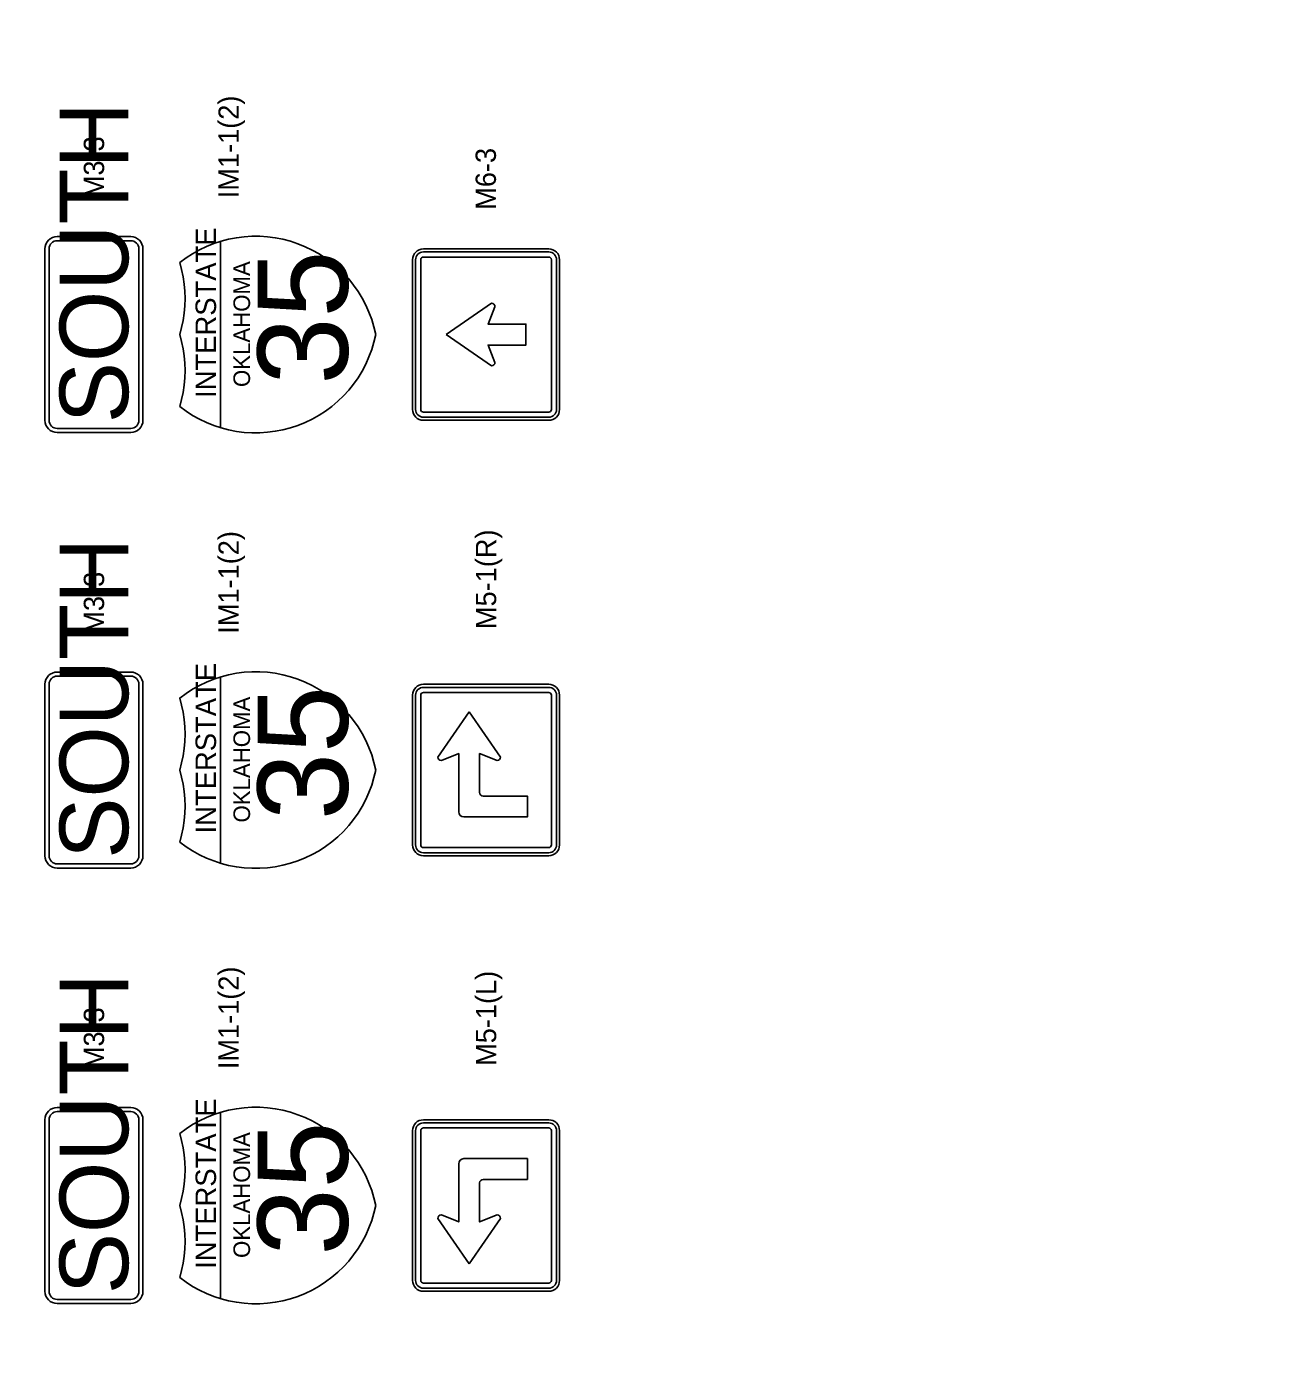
# Model space of a CAD drawing. Extents: x 2135767 to 2151731, y 141839 to 175894.
# Drawn here: x 2137979.7 to 2138264.3, y 170041.1 to 170345.9 of the extents above; entities that cross this region are included whole.
import ezdxf

# ---------------------------------------------------------------- set-up
doc = ezdxf.new("R2010")
doc.units = 0
doc.layers.add('PR_Phasing_Detour_1', color=7, linetype='Continuous')

msp = doc.modelspace()

# ---------------------------------------------------------------- linework, layer by layer
at = {"layer": 'PR_Phasing_Detour_1'}
for p, q in [((2138003.64, 170297.62), (2137986.76, 170297.62)), ((2138003.64, 170296.68), (2137986.76, 170296.68)), ((2138024.26, 170253.71), (2138024.26, 170296.55)), ((2137983.95, 170294.81), (2137983.95, 170255.43)), ((2137984.89, 170294.81), (2137984.89, 170255.43)), ((2138005.51, 170255.43), (2138005.51, 170294.81)), ((2138006.45, 170255.43), (2138006.45, 170294.81)), ((2138099.58, 170294.81), (2138070.82, 170294.81)), ((2138099.58, 170294.1), (2138070.82, 170294.1)), ((2138099.58, 170294.1), (2138070.82, 170294.1)), ((2138070.82, 170292.93), (2138099.58, 170292.93)), ((2138070.82, 170292.93), (2138099.58, 170292.93)), ((2138068.32, 170292.31), (2138068.32, 170257.92)), ((2138069.03, 170292.31), (2138069.03, 170257.92)), ((2138069.03, 170292.31), (2138069.03, 170257.92)), ((2138070.2, 170257.92), (2138070.2, 170292.31)), ((2138070.2, 170257.92), (2138070.2, 170292.31)), ((2138100.2, 170292.31), (2138100.2, 170257.92)), ((2138100.2, 170292.31), (2138100.2, 170257.92)), ((2138101.37, 170257.92), (2138101.37, 170292.31)), ((2138101.37, 170257.92), (2138101.37, 170292.31)), ((2138102.07, 170257.92), (2138102.07, 170292.31)), ((2138086.45, 170282.31), (2138076.06, 170275.12)), ((2138085.65, 170277.52), (2138087.24, 170281.51)), ((2138094.34, 170277.52), (2138085.65, 170277.52)), ((2138094.34, 170272.72), (2138094.34, 170277.52)), ((2138076.06, 170275.12), (2138086.45, 170267.93)), ((2138087.24, 170268.73), (2138085.65, 170272.72)), ((2138085.65, 170272.72), (2138094.34, 170272.72)), ((2138099.58, 170257.31), (2138070.82, 170257.31)), ((2138099.58, 170257.31), (2138070.82, 170257.31)), ((2138070.82, 170256.13), (2138099.58, 170256.13)), ((2138070.82, 170256.13), (2138099.58, 170256.13)), ((2137986.76, 170253.56), (2138003.64, 170253.56)), ((2138070.82, 170255.43), (2138099.58, 170255.43)), ((2137986.76, 170252.62), (2138003.64, 170252.62)), ((2138003.64, 170197.62), (2137986.76, 170197.62)), ((2138003.64, 170196.68), (2137986.76, 170196.68)), ((2138024.26, 170153.71), (2138024.26, 170196.55)), ((2137983.95, 170194.81), (2137983.95, 170155.43)), ((2137984.89, 170194.81), (2137984.89, 170155.43)), ((2138005.51, 170155.43), (2138005.51, 170194.81)), ((2138006.45, 170155.43), (2138006.45, 170194.81)), ((2138068.32, 170192.31), (2138068.32, 170157.92)), ((2138069.03, 170192.31), (2138069.03, 170157.92)), ((2138069.03, 170192.31), (2138069.03, 170157.92)), ((2138070.2, 170192.31), (2138070.2, 170157.92)), ((2138070.2, 170157.92), (2138070.2, 170192.31)), ((2138099.58, 170194.81), (2138070.82, 170194.81)), ((2138099.58, 170194.1), (2138070.82, 170194.1)), ((2138099.58, 170194.1), (2138070.82, 170194.1)), ((2138099.58, 170192.93), (2138070.82, 170192.93)), ((2138070.82, 170192.93), (2138099.58, 170192.93)), ((2138100.2, 170157.92), (2138100.2, 170192.31)), ((2138100.2, 170192.31), (2138100.2, 170157.92)), ((2138101.37, 170157.92), (2138101.37, 170192.31)), ((2138101.37, 170157.92), (2138101.37, 170192.31)), ((2138102.07, 170157.92), (2138102.07, 170192.31)), ((2138074.14, 170178.09), (2138081.33, 170188.48)), ((2138081.33, 170188.48), (2138088.52, 170178.09)), ((2138078.93, 170178.89), (2138074.94, 170177.29)), ((2138078.93, 170165.54), (2138078.93, 170178.89)), ((2138087.72, 170177.29), (2138083.73, 170178.89)), ((2138083.73, 170178.89), (2138083.73, 170169.94)), ((2138084.53, 170169.14), (2138094.69, 170169.14)), ((2138094.69, 170169.14), (2138094.69, 170164.35)), ((2138094.69, 170164.35), (2138080.13, 170164.35)), ((2138070.82, 170157.31), (2138099.58, 170157.31)), ((2138099.58, 170157.31), (2138070.82, 170157.31)), ((2138070.82, 170156.13), (2138099.58, 170156.13)), ((2138070.82, 170156.13), (2138099.58, 170156.13)), ((2138070.82, 170155.43), (2138099.58, 170155.43)), ((2137986.76, 170153.56), (2138003.64, 170153.56)), ((2137986.76, 170152.62), (2138003.64, 170152.62)), ((2138003.64, 170097.62), (2137986.76, 170097.62)), ((2137983.95, 170094.81), (2137983.95, 170055.43)), ((2137984.89, 170094.81), (2137984.89, 170055.43)), ((2138003.64, 170096.68), (2137986.76, 170096.68)), ((2138005.51, 170055.43), (2138005.51, 170094.81)), ((2138006.45, 170055.43), (2138006.45, 170094.81)), ((2138024.26, 170053.71), (2138024.26, 170096.55)), ((2138099.58, 170094.81), (2138070.82, 170094.81)), ((2138068.32, 170092.31), (2138068.32, 170057.92)), ((2138069.03, 170092.31), (2138069.03, 170057.92)), ((2138069.03, 170092.31), (2138069.03, 170057.92)), ((2138070.2, 170092.31), (2138070.2, 170057.92)), ((2138070.2, 170057.92), (2138070.2, 170092.31)), ((2138099.58, 170094.1), (2138070.82, 170094.1)), ((2138099.58, 170094.1), (2138070.82, 170094.1)), ((2138099.58, 170092.93), (2138070.82, 170092.93)), ((2138070.82, 170092.93), (2138099.58, 170092.93)), ((2138100.2, 170057.92), (2138100.2, 170092.31)), ((2138100.2, 170092.31), (2138100.2, 170057.92)), ((2138101.37, 170057.92), (2138101.37, 170092.31)), ((2138101.37, 170057.92), (2138101.37, 170092.31)), ((2138102.07, 170057.92), (2138102.07, 170092.31)), ((2138094.69, 170085.89), (2138080.13, 170085.89)), ((2138094.69, 170081.1), (2138094.69, 170085.89)), ((2138078.93, 170084.69), (2138078.93, 170071.35)), ((2138083.73, 170071.35), (2138083.73, 170080.3)), ((2138084.53, 170081.1), (2138094.69, 170081.1)), ((2138074.14, 170072.15), (2138081.33, 170061.76)), ((2138078.93, 170071.35), (2138074.94, 170072.94)), ((2138081.33, 170061.76), (2138088.52, 170072.15)), ((2138087.72, 170072.94), (2138083.73, 170071.35)), ((2138070.82, 170057.31), (2138099.58, 170057.31)), ((2138099.58, 170057.31), (2138070.82, 170057.31)), ((2138070.82, 170056.13), (2138099.58, 170056.13)), ((2138070.82, 170056.13), (2138099.58, 170056.13)), ((2138070.82, 170055.43), (2138099.58, 170055.43)), ((2137986.76, 170053.56), (2138003.64, 170053.56)), ((2137986.76, 170052.62), (2138003.64, 170052.62))]:
    msp.add_line(p, q, dxfattribs=at)
for points in [[(2138014.89, 170258.59), (2138016.33, 170257.52), (2138017.84, 170256.55), (2138019.4, 170255.68), (2138021.02, 170254.9), (2138022.69, 170254.24), (2138024.39, 170253.68), (2138026.12, 170253.23), (2138027.89, 170252.89), (2138029.66, 170252.66), (2138031.45, 170252.55), (2138033.25, 170252.55), (2138035.04, 170252.67), (2138036.82, 170252.9), (2138038.58, 170253.24), (2138040.31, 170253.7), (2138042.01, 170254.26), (2138043.68, 170254.93), (2138045.29, 170255.71), (2138046.86, 170256.59), (2138048.36, 170257.56), (2138049.8, 170258.63), (2138051.17, 170259.79), (2138052.46, 170261.04), (2138053.67, 170262.36), (2138054.79, 170263.76), (2138055.82, 170265.22), (2138056.76, 170266.75), (2138057.6, 170268.34), (2138058.33, 170269.98), (2138058.96, 170271.66), (2138059.48, 170273.37), (2138059.89, 170275.12), (2138059.48, 170276.86), (2138058.96, 170278.58), (2138058.33, 170280.26), (2138057.6, 170281.9), (2138056.76, 170283.48), (2138055.82, 170285.01), (2138054.79, 170286.48), (2138053.67, 170287.88), (2138052.46, 170289.2), (2138051.17, 170290.44), (2138049.8, 170291.6), (2138048.36, 170292.67), (2138046.86, 170293.65), (2138045.29, 170294.53), (2138043.68, 170295.3), (2138042.01, 170295.97), (2138040.31, 170296.54), (2138038.58, 170296.99), (2138036.82, 170297.34), (2138035.04, 170297.57), (2138033.25, 170297.68), (2138031.45, 170297.69), (2138029.66, 170297.57), (2138027.89, 170297.35), (2138026.12, 170297.01), (2138024.39, 170296.56), (2138022.69, 170296), (2138021.02, 170295.33), (2138019.4, 170294.56), (2138017.84, 170293.69), (2138016.33, 170292.72), (2138014.89, 170291.65), (2138015.33, 170290.03), (2138015.68, 170288.39), (2138015.93, 170286.73), (2138016.08, 170285.06), (2138016.13, 170283.38), (2138016.08, 170281.71), (2138015.93, 170280.04), (2138015.68, 170278.38), (2138015.33, 170276.74), (2138014.89, 170275.12), (2138015.33, 170273.5), (2138015.68, 170271.86), (2138015.93, 170270.2), (2138016.08, 170268.53), (2138016.13, 170266.85), (2138016.08, 170265.18), (2138015.93, 170263.5), (2138015.68, 170261.85), (2138015.33, 170260.2), (2138014.89, 170258.59)], [(2138086.45, 170282.31), (2138076.06, 170275.12)], [(2138087.24, 170268.73), (2138085.65, 170272.72), (2138094.34, 170272.72), (2138094.34, 170277.52), (2138085.65, 170277.52), (2138087.24, 170281.51)], [(2138076.06, 170275.12), (2138086.45, 170267.93)], [(2138014.89, 170158.59), (2138016.33, 170157.52), (2138017.84, 170156.55), (2138019.4, 170155.68), (2138021.02, 170154.9), (2138022.69, 170154.24), (2138024.39, 170153.68), (2138026.12, 170153.23), (2138027.89, 170152.89), (2138029.66, 170152.66), (2138031.45, 170152.55), (2138033.25, 170152.55), (2138035.04, 170152.67), (2138036.82, 170152.9), (2138038.58, 170153.24), (2138040.31, 170153.7), (2138042.01, 170154.26), (2138043.68, 170154.93), (2138045.29, 170155.71), (2138046.86, 170156.59), (2138048.36, 170157.56), (2138049.8, 170158.63), (2138051.17, 170159.79), (2138052.46, 170161.04), (2138053.67, 170162.36), (2138054.79, 170163.76), (2138055.82, 170165.22), (2138056.76, 170166.75), (2138057.6, 170168.34), (2138058.33, 170169.98), (2138058.96, 170171.66), (2138059.48, 170173.37), (2138059.89, 170175.12), (2138059.48, 170176.86), (2138058.96, 170178.58), (2138058.33, 170180.26), (2138057.6, 170181.9), (2138056.76, 170183.48), (2138055.82, 170185.01), (2138054.79, 170186.48), (2138053.67, 170187.88), (2138052.46, 170189.2), (2138051.17, 170190.44), (2138049.8, 170191.6), (2138048.36, 170192.67), (2138046.86, 170193.65), (2138045.29, 170194.53), (2138043.68, 170195.3), (2138042.01, 170195.97), (2138040.31, 170196.54), (2138038.58, 170196.99), (2138036.82, 170197.34), (2138035.04, 170197.57), (2138033.25, 170197.68), (2138031.45, 170197.69), (2138029.66, 170197.57), (2138027.89, 170197.35), (2138026.12, 170197.01), (2138024.39, 170196.56), (2138022.69, 170196), (2138021.02, 170195.33), (2138019.4, 170194.56), (2138017.84, 170193.69), (2138016.33, 170192.72), (2138014.89, 170191.65), (2138015.33, 170190.03), (2138015.68, 170188.39), (2138015.93, 170186.73), (2138016.08, 170185.06), (2138016.13, 170183.38), (2138016.08, 170181.71), (2138015.93, 170180.04), (2138015.68, 170178.38), (2138015.33, 170176.74), (2138014.89, 170175.12), (2138015.33, 170173.5), (2138015.68, 170171.86), (2138015.93, 170170.2), (2138016.08, 170168.53), (2138016.13, 170166.85), (2138016.08, 170165.18), (2138015.93, 170163.5), (2138015.68, 170161.85), (2138015.33, 170160.2), (2138014.89, 170158.59)], [(2138074.14, 170178.09), (2138081.33, 170188.48)], [(2138081.33, 170188.48), (2138088.52, 170178.09)], [(2138078.93, 170165.54), (2138078.93, 170178.89), (2138074.94, 170177.29)], [(2138087.72, 170177.29), (2138083.73, 170178.89), (2138083.73, 170169.94)], [(2138084.53, 170169.14), (2138094.69, 170169.14), (2138094.69, 170164.35), (2138080.13, 170164.35)], [(2138014.89, 170058.59), (2138016.33, 170057.52), (2138017.84, 170056.55), (2138019.4, 170055.68), (2138021.02, 170054.9), (2138022.69, 170054.24), (2138024.39, 170053.68), (2138026.12, 170053.23), (2138027.89, 170052.89), (2138029.66, 170052.66), (2138031.45, 170052.55), (2138033.25, 170052.55), (2138035.04, 170052.67), (2138036.82, 170052.9), (2138038.58, 170053.24), (2138040.31, 170053.7), (2138042.01, 170054.26), (2138043.68, 170054.93), (2138045.29, 170055.71), (2138046.86, 170056.59), (2138048.36, 170057.56), (2138049.8, 170058.63), (2138051.17, 170059.79), (2138052.46, 170061.04), (2138053.67, 170062.36), (2138054.79, 170063.76), (2138055.82, 170065.22), (2138056.76, 170066.75), (2138057.6, 170068.34), (2138058.33, 170069.98), (2138058.96, 170071.66), (2138059.48, 170073.37), (2138059.89, 170075.12), (2138059.48, 170076.86), (2138058.96, 170078.58), (2138058.33, 170080.26), (2138057.6, 170081.9), (2138056.76, 170083.48), (2138055.82, 170085.01), (2138054.79, 170086.48), (2138053.67, 170087.88), (2138052.46, 170089.2), (2138051.17, 170090.44), (2138049.8, 170091.6), (2138048.36, 170092.67), (2138046.86, 170093.65), (2138045.29, 170094.53), (2138043.68, 170095.3), (2138042.01, 170095.97), (2138040.31, 170096.54), (2138038.58, 170096.99), (2138036.82, 170097.34), (2138035.04, 170097.57), (2138033.25, 170097.68), (2138031.45, 170097.69), (2138029.66, 170097.57), (2138027.89, 170097.35), (2138026.12, 170097.01), (2138024.39, 170096.56), (2138022.69, 170096), (2138021.02, 170095.33), (2138019.4, 170094.56), (2138017.84, 170093.69), (2138016.33, 170092.72), (2138014.89, 170091.65), (2138015.33, 170090.03), (2138015.68, 170088.39), (2138015.93, 170086.73), (2138016.08, 170085.06), (2138016.13, 170083.38), (2138016.08, 170081.71), (2138015.93, 170080.04), (2138015.68, 170078.38), (2138015.33, 170076.74), (2138014.89, 170075.12), (2138015.33, 170073.5), (2138015.68, 170071.86), (2138015.93, 170070.2), (2138016.08, 170068.53), (2138016.13, 170066.85), (2138016.08, 170065.18), (2138015.93, 170063.5), (2138015.68, 170061.85), (2138015.33, 170060.2), (2138014.89, 170058.59)], [(2138084.53, 170081.1), (2138094.69, 170081.1), (2138094.69, 170085.89), (2138080.13, 170085.89)], [(2138078.93, 170084.69), (2138078.93, 170071.35), (2138074.94, 170072.94)], [(2138087.72, 170072.94), (2138083.73, 170071.35), (2138083.73, 170080.3)], [(2138074.14, 170072.15), (2138081.33, 170061.76)], [(2138081.33, 170061.76), (2138088.52, 170072.15)]]:
    msp.add_lwpolyline(points, dxfattribs=at)
msp.add_circle((2140069.54, 171591.41), 4302.23, dxfattribs=at)
for centre, radius, start, end in [((2137986.76, 170294.81), 2.81, 90, 180), ((2137986.76, 170294.81), 1.87, 90, 180), ((2138003.64, 170294.81), 2.81, 360, 90), ((2138003.64, 170294.81), 1.87, 360, 90), ((2138070.82, 170292.31), 2.49, 90, 180), ((2138070.82, 170292.31), 1.79, 90, 180), ((2138070.82, 170292.31), 1.79, 90, 180), ((2138070.82, 170292.31), 0.618, 90, 180), ((2138070.82, 170292.31), 0.618, 90, 180), ((2138099.58, 170292.31), 2.49, 360, 90), ((2138099.58, 170292.31), 1.79, 360, 90), ((2138099.58, 170292.31), 1.79, 360, 90), ((2138099.58, 170292.31), 0.618, 360, 90), ((2138099.58, 170292.31), 0.618, 360, 90), ((2138086.45, 170281.51), 0.799, 360, 90), ((2138086.45, 170281.51), 0.799, 360, 90), ((2138086.45, 170268.73), 0.799, 270, 360), ((2138086.45, 170268.73), 0.799, 270, 360), ((2138070.82, 170257.92), 2.49, 180, 270), ((2138070.82, 170257.92), 1.79, 180, 270), ((2138070.82, 170257.92), 1.79, 180, 270), ((2138070.82, 170257.92), 0.618, 180, 270), ((2138070.82, 170257.92), 0.618, 180, 270), ((2138099.58, 170257.92), 2.49, 270, 360), ((2138099.58, 170257.92), 1.79, 270, 360), ((2138099.58, 170257.92), 0.618, 270, 360), ((2138099.58, 170257.92), 1.79, 270, 360), ((2138099.58, 170257.92), 0.618, 270, 360), ((2137986.76, 170255.43), 2.81, 180, 270), ((2137986.76, 170255.43), 1.87, 180, 270), ((2138003.64, 170255.43), 1.87, 270, 360), ((2138003.64, 170255.43), 2.81, 270, 360), ((2137986.76, 170194.81), 2.81, 90, 180), ((2137986.76, 170194.81), 1.87, 90, 180), ((2138003.64, 170194.81), 2.81, 360, 90), ((2138003.64, 170194.81), 1.87, 360, 90), ((2138070.82, 170192.31), 2.49, 90, 180), ((2138070.82, 170192.31), 1.79, 90, 180), ((2138070.82, 170192.31), 1.79, 90, 180), ((2138070.82, 170192.31), 0.618, 90, 180), ((2138070.82, 170192.31), 0.618, 90, 180), ((2138099.58, 170192.31), 2.49, 360, 90), ((2138099.58, 170192.31), 1.79, 360, 90), ((2138099.58, 170192.31), 1.79, 360, 90), ((2138099.58, 170192.31), 0.618, 360, 90), ((2138099.58, 170192.31), 0.618, 360, 90), ((2138074.94, 170178.09), 0.799, 180, 270), ((2138074.94, 170178.09), 0.799, 180, 270), ((2138087.72, 170178.09), 0.799, 270, 360), ((2138087.72, 170178.09), 0.799, 270, 360), ((2138084.53, 170169.94), 0.799, 180, 270), ((2138084.53, 170169.94), 0.799, 180, 270), ((2138080.13, 170165.54), 1.2, 180, 270), ((2138080.13, 170165.54), 1.2, 180, 270), ((2137986.76, 170155.43), 2.81, 180, 270), ((2137986.76, 170155.43), 1.87, 180, 270), ((2138003.64, 170155.43), 1.87, 270, 360), ((2138003.64, 170155.43), 2.81, 270, 360), ((2138070.82, 170157.92), 2.49, 180, 270), ((2138070.82, 170157.92), 1.79, 180, 270), ((2138070.82, 170157.92), 1.79, 180, 270), ((2138070.82, 170157.92), 0.618, 180, 270), ((2138070.82, 170157.92), 0.618, 180, 270), ((2138099.58, 170157.92), 2.49, 270, 360), ((2138099.58, 170157.92), 1.79, 270, 360), ((2138099.58, 170157.92), 0.618, 270, 360), ((2138099.58, 170157.92), 1.79, 270, 360), ((2138099.58, 170157.92), 0.618, 270, 360), ((2137986.76, 170094.81), 2.81, 90, 180), ((2138003.64, 170094.81), 2.81, 360, 90), ((2137986.76, 170094.81), 1.87, 90, 180), ((2138003.64, 170094.81), 1.87, 360, 90), ((2138070.82, 170092.31), 2.49, 90, 180), ((2138099.58, 170092.31), 2.49, 360, 90), ((2138070.82, 170092.31), 1.79, 90, 180), ((2138070.82, 170092.31), 1.79, 90, 180), ((2138070.82, 170092.31), 0.618, 90, 180), ((2138070.82, 170092.31), 0.618, 90, 180), ((2138099.58, 170092.31), 1.79, 360, 90), ((2138099.58, 170092.31), 1.79, 360, 90), ((2138099.58, 170092.31), 0.618, 360, 90), ((2138099.58, 170092.31), 0.618, 360, 90), ((2138080.13, 170084.69), 1.2, 90, 180), ((2138080.13, 170084.69), 1.2, 90, 180), ((2138084.53, 170080.3), 0.799, 90, 180), ((2138084.53, 170080.3), 0.799, 90, 180), ((2138074.94, 170072.15), 0.799, 90, 180), ((2138074.94, 170072.15), 0.799, 90, 180), ((2138087.72, 170072.15), 0.799, 360, 90), ((2138087.72, 170072.15), 0.799, 360, 90), ((2138070.82, 170057.92), 2.49, 180, 270), ((2138070.82, 170057.92), 1.79, 180, 270), ((2138070.82, 170057.92), 1.79, 180, 270), ((2138070.82, 170057.92), 0.618, 180, 270), ((2138070.82, 170057.92), 0.618, 180, 270), ((2138099.58, 170057.92), 2.49, 270, 360), ((2138099.58, 170057.92), 1.79, 270, 360), ((2138099.58, 170057.92), 0.618, 270, 360), ((2138099.58, 170057.92), 1.79, 270, 360), ((2138099.58, 170057.92), 0.618, 270, 360), ((2137986.76, 170055.43), 2.81, 180, 270), ((2137986.76, 170055.43), 1.87, 180, 270), ((2138003.64, 170055.43), 1.87, 270, 360), ((2138003.64, 170055.43), 2.81, 270, 360)]:
    msp.add_arc(centre, radius, start, end, dxfattribs=at)

# ---------------------------------------------------------------- texts
for s, height, p in [('IM1-1(2)', 4.664, (2138028.45, 170306.43)), ('SOUTH', 15.75, (2138003.07, 170254.75)), ('M3-3', 4.664, (2137997.53, 170306.43)), ('M6-3', 4.664, (2138087.47, 170303.77)), ('INTERSTATE', 4.704, (2138023.23, 170260.57)), ('35', 20.7, (2138053.46, 170263.63)), ('OKLAHOMA', 3.812, (2138031.03, 170263.07)), ('IM1-1(2)', 4.664, (2138028.45, 170206.43)), ('M5-1(R)', 4.664, (2138087.53, 170207.49)), ('SOUTH', 15.75, (2138003.07, 170154.75)), ('M3-3', 4.664, (2137997.53, 170206.43)), ('INTERSTATE', 4.704, (2138023.23, 170160.57)), ('OKLAHOMA', 3.812, (2138031.03, 170163.07)), ('35', 20.7, (2138053.46, 170163.63)), ('IM1-1(2)', 4.664, (2138028.45, 170106.43)), ('M5-1(L)', 4.664, (2138087.53, 170107.18)), ('SOUTH', 15.75, (2138003.07, 170054.75)), ('M3-3', 4.664, (2137997.53, 170106.43)), ('INTERSTATE', 4.704, (2138023.23, 170060.57)), ('OKLAHOMA', 3.812, (2138031.03, 170063.07)), ('35', 20.7, (2138053.46, 170063.63))]:
    msp.add_text(s, height=height, rotation=90, dxfattribs=at).set_placement(p)

doc.saveas('drawing.dxf')
